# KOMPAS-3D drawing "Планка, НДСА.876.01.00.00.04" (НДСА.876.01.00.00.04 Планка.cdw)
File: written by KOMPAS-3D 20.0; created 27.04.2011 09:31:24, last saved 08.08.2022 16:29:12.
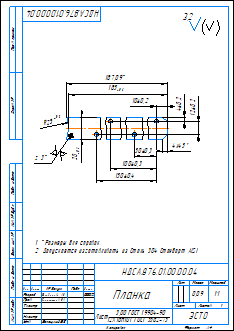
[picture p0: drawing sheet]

Sheet 1: A4, portrait

Document properties: Автор: Мочегов И.Н.; Организация: ЭСТО-Вакуум; Полное имя файла: C:\Users\cherbakova\Desktop\Барсук\НДСА.876.00.00.00.00 Нагреватель горизонтальный\НДСА.876.01.00.00.04 Планка.cdw; Масса: 0.086824; Знак неуказанной шероховатости: 4; Параметр неуказанной шероховатости: 3,2; 309010472574: <item xmlns="http://appius.ru/pdm" xmlns:xs="http://www.w3.org/2001/XMLSchema" xmlns:xsi="http://www.w3.org/2001/XMLSchema-instance" xsi:type="item">  <element xmlns:d2p1="http://v8.1c.ru/8.1/data/enterprise/current-config" xsi:type="d2p1:CatalogRef.aps_Элемен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; 309010472674: <item xmlns="http://appius.ru/pdm" xmlns:xs="http://www.w3.org/2001/XMLSchema" xmlns:xsi="http://www.w3.org/2001/XMLSchema-instance" xsi:type="item">  <element xmlns:d2p1="http://v8.1c.ru/8.1/data/enterprise/current-config" xsi:type="d2p1:CatalogRef.aps_Элемен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; 255550438450: <item xmlns="http://appius.ru/pdm" xmlns:xs="http://www.w3.org/2001/XMLSchema" xmlns:xsi="http://www.w3.org/2001/XMLSchema-instance" xsi:type="item">  <element xmlns:d2p1="http://v8.1c.ru/8.1/data/enterprise/current-config" xsi:type="d2p1:CatalogRef.aps_Элемен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; 255550438550: <item xmlns="http://appius.ru/pdm" xmlns:xs="http://www.w3.org/2001/XMLSchema" xmlns:xsi="http://www.w3.org/2001/XMLSchema-instance" xsi:type="item">  <element xmlns:d2p1="http://v8.1c.ru/8.1/data/enterprise/current-config" xsi:type="d2p1:CatalogRef.aps_Элемен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; 231621970029: <item xmlns="http://appius.ru/pdm" xmlns:xs="http://www.w3.org/2001/XMLSchema" xmlns:xsi="http://www.w3.org/2001/XMLSchema-instance" xsi:type="item">  <element xmlns:d2p1="http://v8.1c.ru/8.1/data/enterprise/current-config" xsi:type="d2p1:CatalogRef.aps_Элемен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; 231621970129: <item xmlns="http://appius.ru/pdm" xmlns:xs="http://www.w3.org/2001/XMLSchema" xmlns:xsi="http://www.w3.org/2001/XMLSchema-instance" xsi:type="item">  <element xmlns:d2p1="http://v8.1c.ru/8.1/data/enterprise/current-config" xsi:type="d2p1:CatalogRef.aps_Элемен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; 290675641607: <item xmlns="http://appius.ru/pdm" xmlns:xs="http://www.w3.org/2001/XMLSchema" xmlns:xsi="http://www.w3.org/2001/XMLSchema-instance" xsi:type="item">  <element xmlns:d2p1="http://v8.1c.ru/8.1/data/enterprise/current-config" xsi:type="d2p1:CatalogRef.aps_Элемен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; PLM_CDWXDTO: <item xmlns="http://appius.ru/pdm" xmlns:xs="http://www.w3.org/2001/XMLSchema" xmlns:xsi="http://www.w3.org/2001/XMLSchema-instance" xsi:type="item">  <element xmlns:d2p1="http://v8.1c.ru/8.1/data/enterprise/current-config" xsi:type="d2p1:CatalogRef.aps_Элемен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

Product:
- Part/product: Планка  | designation НДСА.876.01.00.00.04
    Материал: Лист$d3,00 ГОСТ 19904-90;12Х18Н10Т ГОСТ 5582-75$ (density 7900 kg/m3)
    Масса: 0.086824
    Раздел спецификации: Детали
    additional columns: <item xmlns="http://appius.ru/pdm" xmlns:xs="http://www.w3.org/2001/XMLSchema" x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; <item xmlns="http://appius.ru/pdm" xmlns:xs="http://www.w3.org/2001/XMLSchema" x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; <item xmlns="http://appius.ru/pdm" xmlns:xs="http://www.w3.org/2001/XMLSchema" x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; <item xmlns="http://appius.ru/pdm" xmlns:xs="http://www.w3.org/2001/XMLSchema" x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; <item xmlns="http://appius.ru/pdm" xmlns:xs="http://www.w3.org/2001/XMLSchema" x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; <item xmlns="http://appius.ru/pdm" xmlns:xs="http://www.w3.org/2001/XMLSchema" x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
    source file: НДСА.876.01.00.00.04 Планка.cdw

Title block, sheet 1: Наименование: Планка; designation: НДСА.876.01.00.00.04; Материал: Лист 3,00 ГОСТ 19904-90 12Х18Н10Т ГОСТ 5582-75; Масса: 0,09; scale: 1:1; Количество листов документа: 1; organisation: ЭСТО; Форматы листов документа: A4; stored path: C:\Documents and Settings\min\Мои документы\Мои файлы 1C-PDM\5ddefa04-0f1f-400a-bf2b-f35ec2db4c2c\УКРД.772.08.02.00.02 Планка.cdw; Разработал: Щербакова А.В.; Проверил: Горностаев П.А.; Утвердил: Белецкий В.Е.; Разработал, date: 03.08.2022
Table, sheet 1:
  0;Material:V27FFD6AC31654437822AAF34B18F4E49;Sortament:VF71A155B5AD311D7882700508B01A93A^SortamentEx:V898C9E38AB8749C2BC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

Views: Вид 1, Сверху
Referenced files in C:\Users\cherbakova\Desktop\PLM\: НДСА.876.01.00.00.04 Планка.m3d
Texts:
  НДСА.876.01.00.00.04 Планка
Dimensions and other numbers on the sheet: 25; 20; 187,09; 185; 12±0,2; 10±0,2; 150±0,4; 100±0,3; 50±0,3; 4±0,2; 3,2; 1:1; 1; 0,09; 03.08.2022

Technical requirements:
  *Размеры для справок
  Допускается изготавливать из Сталь 304 Стандарт AISI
